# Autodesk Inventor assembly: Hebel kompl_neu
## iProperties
Created: 2006-11
Part Number: Hebel kompl_neu
Cost Center: 0 kg
Document SubType Name: Assembly
Designer: Schmidt
Authority: 0 mm^3
Mass: 542.243 g
Surface Area: 341.667 cm^2
Volume: 69.1636 cm^3
Density: 7.84 g/cm^3
SaveDate: 2004-08-02
SaveTime: 16:43
TotalMass: 0 kg
TotalVolume: 0 mm^3
Author: Schmidt
